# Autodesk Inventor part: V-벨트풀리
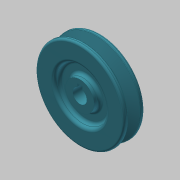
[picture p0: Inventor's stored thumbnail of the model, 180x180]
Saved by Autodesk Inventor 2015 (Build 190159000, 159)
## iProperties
Created: 2019-09
Part Number: V-벨트풀리
Material: 알루미늄 6061
Document SubType Name: Modeling
Designer: mduedu
Density: 1 g/cm^3
Appearance: 커뎃 파란색
Author: mduedu
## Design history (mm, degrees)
sketch "스케치1"
  geometry: L1 (-10, 0)-(10, 0); L2 (10, 0)-(10, 43.5); L3 (10, 43.5)-(-10, 43.5); L4 (-10, 43.5)-(-10, 0); L5 (0, 0)-(0, 43.5); L6 (-5.976, 43.5)-(-2.154, 31); L7 (-2.154, 31)-(2.154, 31); L8 (2.154, 31)-(5.976, 43.5); L9 (-10, 39)-(10, 39); 3 further points
  constraints: 18 end point, 8 point on line, 3 perpendicular, 2 midpoint, 2 parallel, 1 coincident, 1 horizontal, 1 other
  dimensions: "d0" = 87 diameter of L3 L1; "d3" = 12.5 distance between parallel lines of L7 L3; "d4" = 34 deg angle of L8 L6; "d5" = 20 distance between parallel lines of L2 L4; "d6" = 8 distance between parallel lines of L9 L7; "d7" = 9.2 distance of point (4.6, 39) point (-4.6, 39)
revolve "회전1" sketch "스케치1" stored, may be unused: angle "d8" = 90 deg
sketch "스케치2"
  geometry: C1 r 14 at (0, 0); C2 r 25 at (0, 0); 1 further point
  constraints: 2 centre point, 2 coincident
  dimensions: "d9" = 28 diameter of C1; "d10" = 50 diameter of C2
extrude "돌출1" cut sketch "스케치2" distance "d11" = 6; taper "d12" = 0 deg
fillet "모깎기1" dims "d13" = 3
fillet "모깎기2" dims "d14" = 3
fillet "모깎기3" dims "d15" = 0.5, "d16" = 1, "d17" = 2
sketch "스케치3"
  geometry: L1 (-2.5, 6.538)-(2.5, 6.538); L2 (2.5, 6.538)-(2.5, 9.3); L3 (2.5, 9.3)-(-2.5, 9.3); L4 (-2.5, 9.3)-(-2.5, 6.538); A1 r 7 centre (0, 0) between (-2.5, 6.538) and (2.5, 6.538); 1 further point
  constraints: 8 end point, 2 parallel, 2 point on circle, 1 centre point, 1 coincident, 1 horizontal, 1 perpendicular
  dimensions: "d18" = 14 diameter of A1; "d20" = 5 distance of L2.end L3.end; "d21" = 16.3 dimension on A1 L3
extrude "돌출2" cut sketch "스케치3" stored distance "d22" = 6; taper "d23" = 0 deg
node "솔리드1"
mirror "대칭1"
